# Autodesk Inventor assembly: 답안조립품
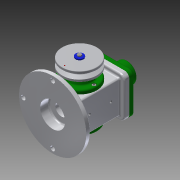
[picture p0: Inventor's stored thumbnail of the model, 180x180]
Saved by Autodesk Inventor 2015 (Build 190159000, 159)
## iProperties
Created: 2019-08
Part Number: 답안조립품
Document SubType Name: Assembly
Designer: a5
Author: a5
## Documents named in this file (18)
- C:\Users\a5\Desktop\490804V1006\답안조립품.iam
- C:\Users\a5\Desktop\490804V1006\본체.ipt
- C:\Users\a5\Desktop\490804V1006\뒤커버.ipt
- C:\Users\a5\Desktop\490804V1006\앞커버.ipt
- C:\Users\a5\Desktop\490804V1006\베어링 17 x 40 x 12.ipt
- C:\Users\a5\Desktop\490804V1006\편심축.ipt
- C:\Users\a5\Desktop\490804V1006\링크.ipt
- C:\Users\a5\Desktop\490804V1006\슬라이더.ipt
- C:\Users\a5\Desktop\490804V1006\클레비스 핀 6 x 22.ipt
- 클레비스 핀 6 x 22.ipt
- C:\Users\a5\Desktop\490804V1006\E-링.ipt
- C:\Users\a5\Desktop\490804V1006\덮개.ipt
- C:\Users\a5\Desktop\490804V1006\볼트 M4 x 8.ipt
- C:\Users\a5\Desktop\490804V1006\오일 실 17 30 8.ipt
- C:\Users\a5\Desktop\490804V1006\키 4 x 4 x 12.ipt
- C:\Users\a5\Desktop\490804V1006\V-벨트풀리.ipt
- C:\Users\a5\Desktop\490804V1006\와셔 4x16.ipt
- C:\Users\a5\Desktop\490804V1006\볼트 M4 x 10.ipt
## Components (2 placed, 2 different names)
1. E-링:1
2. V-벨트풀리:1
